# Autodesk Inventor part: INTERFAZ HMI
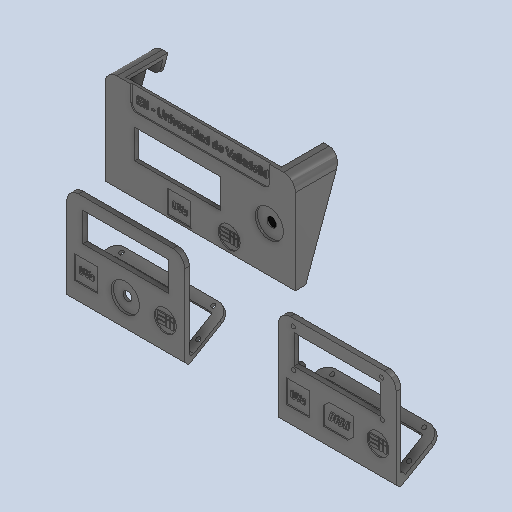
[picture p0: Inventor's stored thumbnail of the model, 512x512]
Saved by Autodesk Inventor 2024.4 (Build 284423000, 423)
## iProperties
Created: 2025-06
Part Number: INTERFAZ HMI
Material: Generic
Document SubType Name: Modeling
Designer: AdminForWorker
Density: 1 g/cm^3
Appearance: Default
Title: INTERFAZ HMI v25
Author: AdminForWorker
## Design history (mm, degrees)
feature "PANTALLA v1"
feature "PANTALLA v2"
feature "PANTALLA  v3"
body "Solid1"
body "Solid2"
body "Solid3"
